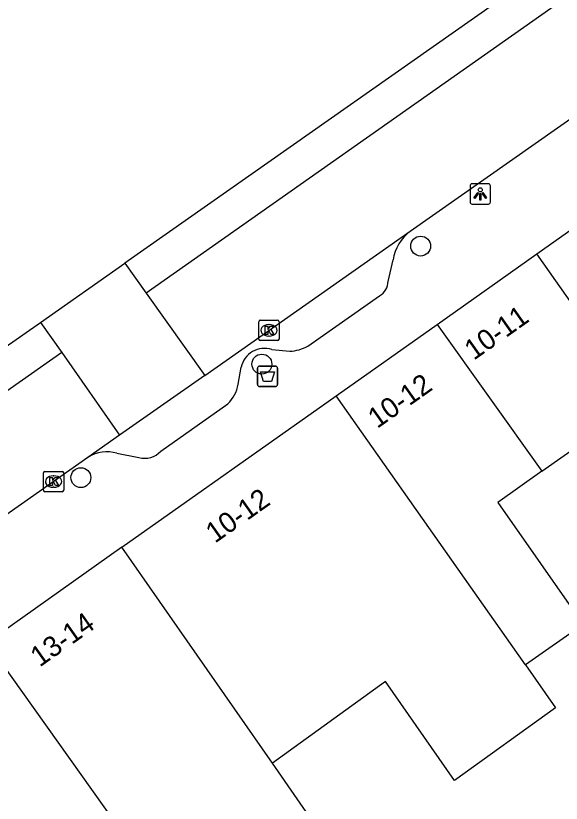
# Model space of a CAD drawing. Extents: x 160664 to 161506, y 382245 to 383288.
# Drawn here: x 160825.76 to 160852.57, y 383155.26 to 383193.99 of the extents above; entities that cross this region are included whole.
import ezdxf

# ---------------------------------------------------------------- set-up
doc = ezdxf.new("R2010")
doc.units = 0
for name, color, linetype in [('IMGEO_Afvalbak', 7, 'Continuous'), ('IMGEO_Boom', 7, 'Continuous'), ('IMGEO_Kolk', 7, 'Continuous'), ('IMGEO_Lichtpunt', 7, 'Continuous'), ('IMGEO_Pand', 7, 'Continuous'), ('IMGEO_Pand_nummerreeks', 7, 'Continuous'), ('IMGEO_Parkeervlak_gesloten', 7, 'Continuous'), ('IMGEO_Rijbaan_lokaal_gesloten', 7, 'Continuous'), ('IMGEO_Rijbaan_lokaal_open', 7, 'Continuous'), ('IMGEO_Voetpad_open', 7, 'Continuous')]:
    doc.layers.add(name, color=color, linetype=linetype)

msp = doc.modelspace()

# ---------------------------------------------------------------- linework, layer by layer
at = {"layer": 'IMGEO_Afvalbak'}
for p, q in [((160837.739, 383176.754), (160838.529, 383176.754)), ((160838.529, 383176.754), (160837.739, 383176.754)), ((160837.639, 383175.854), (160837.639, 383176.654)), ((160837.639, 383176.654), (160837.639, 383175.854)), ((160838.629, 383176.654), (160838.629, 383175.854)), ((160838.629, 383175.854), (160838.629, 383176.654)), ((160838.529, 383175.754), (160837.739, 383175.754)), ((160837.739, 383175.754), (160838.529, 383175.754))]:
    msp.add_line(p, q, dxfattribs=at)
msp.add_lwpolyline([(160837.782, 383176.468), (160838.486, 383176.468), (160838.337, 383175.998), (160837.931, 383175.998), (160837.782, 383176.468)], dxfattribs=at)
for centre, start, end in [((160837.739, 383176.654), 90, 180), ((160837.739, 383176.654), 90, 180), ((160838.529, 383176.654), 0, 90), ((160838.529, 383176.654), 360, 90), ((160837.739, 383175.854), 180, 270), ((160837.739, 383175.854), 180, 270), ((160838.529, 383175.854), 270, 0), ((160838.529, 383175.854), 270, 0)]:
    msp.add_arc(centre, 0.1, start, end, dxfattribs=at)
at = {"layer": 'IMGEO_Boom'}
for centre in [(160845.662, 383182.66), (160837.856, 383176.855), (160828.961, 383171.272)]:
    msp.add_circle(centre, 0.489, dxfattribs=at)
at = {"layer": 'IMGEO_Kolk'}
for p, q in [((160837.703, 383178.09), (160837.703, 383178.942)), ((160837.778, 383179.016), (160838.63, 383179.016)), ((160838.191, 383178.796), (160838.216, 383178.796)), ((160838.704, 383178.942), (160838.704, 383178.09)), ((160838.63, 383178.016), (160837.778, 383178.016)), ((160838.214, 383178.236), (160838.189, 383178.236)), ((160827.117, 383170.654), (160827.117, 383171.506)), ((160827.192, 383171.58), (160828.044, 383171.58)), ((160827.605, 383171.36), (160827.63, 383171.36)), ((160828.118, 383171.506), (160828.118, 383170.654)), ((160828.044, 383170.58), (160827.192, 383170.58)), ((160827.628, 383170.8), (160827.603, 383170.8))]:
    msp.add_line(p, q, dxfattribs=at)
for points in [[(160837.703, 383178.09), (160837.703, 383178.942)], [(160837.778, 383179.016), (160838.63, 383179.016)], [(160838.024, 383178.716), (160838.147, 383178.716), (160838.147, 383178.565), (160838.277, 383178.716), (160838.441, 383178.716), (160838.295, 383178.565), (160838.448, 383178.316), (160838.296, 383178.316), (160838.211, 383178.48), (160838.147, 383178.413), (160838.147, 383178.316), (160838.024, 383178.316), (160838.024, 383178.716)], [(160838.704, 383178.942), (160838.704, 383178.09)], [(160838.63, 383178.016), (160837.778, 383178.016)], [(160827.117, 383170.654), (160827.117, 383171.506)], [(160827.192, 383171.58), (160828.044, 383171.58)], [(160828.118, 383171.506), (160828.118, 383170.654)], [(160827.438, 383171.28), (160827.561, 383171.28), (160827.561, 383171.129), (160827.691, 383171.28), (160827.855, 383171.28), (160827.709, 383171.129), (160827.862, 383170.88), (160827.71, 383170.88), (160827.625, 383171.044), (160827.561, 383170.977), (160827.561, 383170.88), (160827.438, 383170.88), (160827.438, 383171.28)], [(160828.044, 383170.58), (160827.192, 383170.58)]]:
    msp.add_lwpolyline(points, dxfattribs=at)
for centre, start, end in [((160837.78, 383178.94), 91.552, 178.448), ((160837.78, 383178.94), 91.552, 178.448), ((160838.628, 383178.94), 1.552, 88.448), ((160838.628, 383178.94), 1.552, 88.448), ((160837.78, 383178.092), 181.552, 268.448), ((160837.78, 383178.092), 181.552, 268.448), ((160838.628, 383178.092), 271.552, 358.448), ((160838.628, 383178.092), 271.552, 358.448), ((160827.194, 383171.504), 91.552, 178.448), ((160827.194, 383171.504), 91.552, 178.448), ((160828.042, 383171.504), 1.552, 88.448), ((160828.042, 383171.504), 1.552, 88.448), ((160827.194, 383170.656), 181.552, 268.448), ((160827.194, 383170.656), 181.552, 268.448), ((160828.042, 383170.656), 271.552, 358.448), ((160828.042, 383170.656), 271.552, 358.448)]:
    msp.add_arc(centre, 0.0765, start, end, dxfattribs=at)
for centre, major_axis, ratio, start_param, end_param in [((160838.19, 383178.516), (-0.387, 0.002), 0.722429, 4.712389, 7.853982), ((160838.215, 383178.516), (-0.39, 0.002), 0.717154, 1.570796, 4.712389), ((160827.604, 383171.08), (-0.387, 0.002), 0.722429, 4.712389, 7.853982), ((160827.629, 383171.08), (-0.39, 0.002), 0.717154, 1.570796, 4.712389)]:
    msp.add_ellipse(centre, major_axis=major_axis, ratio=ratio, start_param=start_param, end_param=end_param, dxfattribs=at)
at = {"layer": 'IMGEO_Lichtpunt'}
for p, q in [((160848.095, 383185.627), (160848.095, 383184.82)), ((160848.095, 383185.627), (160848.095, 383184.82)), ((160848.997, 383185.722), (160848.189, 383185.722)), ((160848.997, 383185.722), (160848.189, 383185.722)), ((160849.091, 383184.82), (160849.091, 383185.627)), ((160849.091, 383184.82), (160849.091, 383185.627)), ((160848.189, 383184.726), (160848.997, 383184.726)), ((160848.189, 383184.726), (160848.997, 383184.726))]:
    msp.add_line(p, q, dxfattribs=at)
for points in [[(160848.469, 383185.291), (160848.508, 383185.263), (160848.32, 383185.001), (160848.282, 383185.028), (160848.469, 383185.291)], [(160848.571, 383185.243), (160848.618, 383185.243), (160848.618, 383184.921), (160848.571, 383184.921), (160848.571, 383185.243)], [(160848.681, 383185.263), (160848.719, 383185.29), (160848.906, 383185.028), (160848.867, 383185), (160848.681, 383185.263)]]:
    msp.add_lwpolyline(points, dxfattribs=at)
msp.add_circle((160848.594, 383185.425), 0.0994, dxfattribs=at)
for centre, start, end in [((160848.189, 383185.627), 90, 180), ((160848.189, 383185.627), 90, 180), ((160848.997, 383185.627), 0, 90), ((160848.997, 383185.627), 0, 90), ((160848.189, 383184.82), 180, 270), ((160848.189, 383184.82), 180, 270), ((160848.997, 383184.82), 270, 0), ((160848.997, 383184.82), 270, 360)]:
    msp.add_arc(centre, 0.0946, start, end, dxfattribs=at)
at = {"layer": 'IMGEO_Pand'}
for points in [[(160851.374, 383182.272), (160860.186, 383188.504), (160861.86, 383188.217)], [(160846.479, 383178.81), (160851.374, 383182.272)], [(160856.165, 383169.45), (160859.003, 383171.423), (160851.374, 383182.272)], [(160841.512, 383175.298), (160846.479, 383178.81)], [(160846.479, 383178.81), (160851.626, 383171.582)], [(160830.982, 383167.851), (160841.512, 383175.298)], [(160850.814, 383162.057), (160841.512, 383175.298)], [(160851.626, 383171.582), (160853.654, 383173.016), (160856.165, 383169.45)], [(160851.626, 383171.582), (160849.457, 383170.048), (160853.653, 383164.052), (160850.814, 383162.057)], [(160830.982, 383167.851), (160824.34, 383163.154)], [(160838.375, 383157.23), (160830.982, 383167.851)], [(160824.34, 383163.154), (160832.439, 383151.785)], [(160850.814, 383162.057), (160852.292, 383159.952), (160847.331, 383156.373), (160843.935, 383161.242), (160838.375, 383157.23)], [(160847.865, 383143.697), (160843.625, 383149.714), (160840.653, 383153.931), (160838.375, 383157.23)]]:
    msp.add_lwpolyline(points, dxfattribs=at)
at = {"layer": 'IMGEO_Parkeervlak_gesloten'}
for points in [[(160850.335, 383195.323), (160831.12, 383181.818)], [(160825.075, 383177.569), (160826.976, 383178.905)]]:
    msp.add_lwpolyline(points, dxfattribs=at)
at = {"layer": 'IMGEO_Rijbaan_lokaal_gesloten'}
for points in [[(160854.002, 383195.72), (160832.171, 383180.339)], [(160845.145, 383183.392), (160857.428, 383192.02), (160857.418, 383192.034)], [(160835.046, 383176.299), (160845.145, 383183.392)]]:
    msp.add_lwpolyline(points, dxfattribs=at)
at = {"layer": 'IMGEO_Rijbaan_lokaal_open'}
for points in [[(160826.976, 383178.905), (160831.12, 383181.818)], [(160831.12, 383181.818), (160832.171, 383180.339)], [(160832.171, 383180.339), (160835.046, 383176.299)], [(160826.976, 383178.905), (160828.019, 383177.418)], [(160828.019, 383177.418), (160811.719, 383165.96)], [(160828.019, 383177.418), (160830.865, 383173.362)], [(160835.046, 383176.299), (160830.865, 383173.362)], [(160830.865, 383173.362), (160829.309, 383172.269)], [(160829.309, 383172.269), (160824.986, 383169.233), (160821.229, 383166.594), (160815.074, 383162.271), (160814.538, 383161.889)]]:
    msp.add_lwpolyline(points, dxfattribs=at)
at = {"layer": 'IMGEO_Voetpad_open'}
for points in [[(160844.067, 383180.926), (160844.308, 383181.98)], [(160840.117, 383177.74), (160843.647, 383180.215)], [(160838.346, 383177.57), (160839.235, 383177.485)], [(160836.69, 383175.861), (160836.839, 383176.7)], [(160832.894, 383172.569), (160836.186, 383174.907)], [(160830.736, 383172.47), (160831.803, 383172.259)]]:
    msp.add_lwpolyline(points, dxfattribs=at)
for centre, radius, start, end in [((160846.527, 383181.618), 2.249, 127.9352, 170.7479), ((160843.191, 383180.964), 0.877, 301.3283, 357.5295), ((160837.975, 383176.473), 1.158, 71.3191, 168.6771), ((160839.103, 383179.593), 2.113, 273.5749, 298.6759), ((160835.017, 383176.135), 1.695, 313.5986, 350.7062), ((160830.236, 383170.853), 1.692, 72.8148, 123.2205), ((160832.09, 383173.325), 1.103, 254.9377, 316.7866)]:
    msp.add_arc(centre, radius, start, end, dxfattribs=at)

# ---------------------------------------------------------------- texts
at = {"layer": 'IMGEO_Pand_nummerreeks'}
for s, rotation, p in [('10-11', 35.2713, (160848.272, 383177.016)), ('10-12', 35.2656, (160843.525, 383173.66)), ('10-12', 35.2713, (160835.552, 383168.02)), ('13-14', 35.2656, (160826.935, 383161.927))]:
    msp.add_text(s, height=1, rotation=rotation, dxfattribs=at).set_placement(p)

doc.saveas('drawing.dxf')
